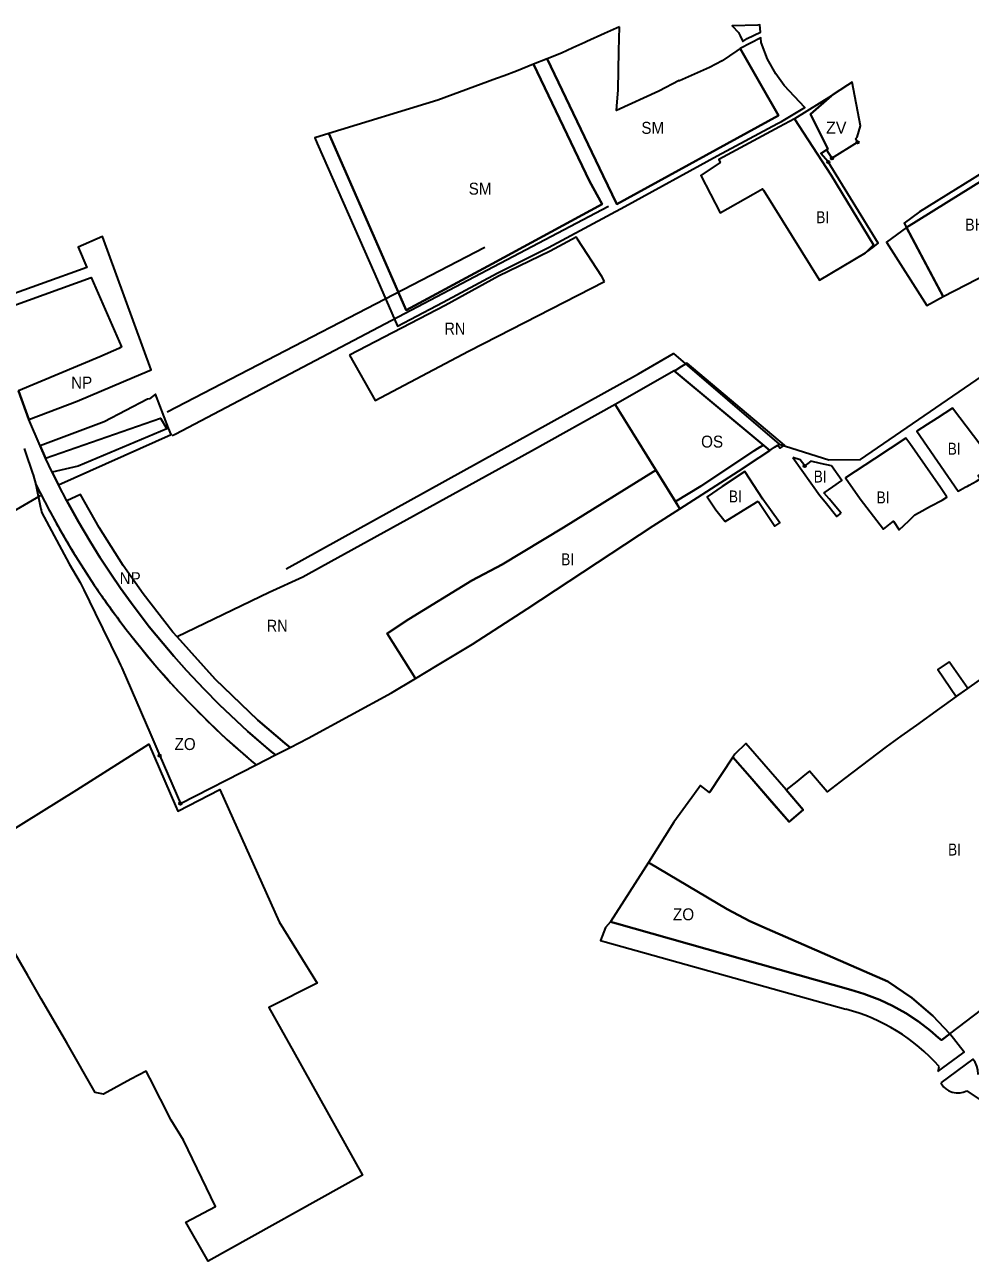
# Model space of a CAD drawing. Extents: x -650276 to -642489, y -1074311 to -1066658.
# Drawn here: x -649019 to -648072, y -1071627 to -1070387 of the extents above; entities that cross this region are included whole.
import ezdxf

# ---------------------------------------------------------------- set-up
doc = ezdxf.new("R2010")
doc.units = 0
doc.header["$LTSCALE"] = 4.8
doc.header["$PDMODE"] = 32
doc.header["$PDSIZE"] = 2.4
for name, color, linetype, lineweight in [('1', 7, 'Continuous', 35), ('15', 7, 'Continuous', 35), ('18', 7, 'Continuous', 35), ('2', 7, 'Continuous', 35), ('24', 7, 'Continuous', 35), ('40', 7, 'Continuous', 35), ('42', 7, 'Continuous', 35), ('48', 7, 'Continuous', 35), ('54', 7, 'Continuous', 35), ('7', 7, 'Continuous', 35), ('9', 7, 'Continuous', 35)]:
    doc.layers.add(name, color=color, linetype=linetype, lineweight=lineweight)
doc.layers.add('62', color=7, linetype='Continuous')
doc.layers.add('63', color=7, linetype='Continuous')

msp = doc.modelspace()

# ---------------------------------------------------------------- linework, layer by layer
at = {"layer": '1'}
msp.add_lwpolyline([(-648098.637, -1070659.682), (-648007.838, -1070612.851), (-648019, -1070518), (-648135.47, -1070590.61), (-648105.98, -1070645.91)], close=True, dxfattribs=at)
at = {"layer": '15'}
for p, q in [((-648303.631, -1070834.849), (-648283.19, -1070821.23)), ((-648272.453, -1070814.072), (-648271.1, -1070813.17))]:
    msp.add_line(p, q, dxfattribs=at)
for points in [[(-648303.705, -1070395.035), (-648302.028, -1070398.436), (-648299.32, -1070403.93), (-648295.18, -1070401.23), (-648281.907, -1070394.762), (-648282.582, -1070387.276), (-648284.37, -1070387.85), (-648310.275, -1070388.476)], [(-648550.72, -1070626.869), (-648636.757, -1070673.431), (-648655.178, -1070631.294), (-648714.161, -1070496.376), (-648728.255, -1070500.709), (-648725.835, -1070506.221), (-648668.207, -1070637.453), (-648645.331, -1070689.546), (-648632.652, -1070682.82), (-648599.66, -1070665.32), (-648545.76, -1070636.22), (-648494.04, -1070610.73), (-648417.855, -1070569.57), (-648325.21, -1070518.84), (-648264.56, -1070486.34), (-648260.57, -1070484.2), (-648237.475, -1070470.361), (-648257.96, -1070448.17), (-648266.416, -1070436.404), (-648274.808, -1070421.647), (-648280.974, -1070405.11), (-648281.388, -1070400.523), (-648302.01, -1070411.05), (-648282.01, -1070446.35), (-648263.859, -1070478.393), (-648425.835, -1070567.021), (-648439.409, -1070538.729), (-648495.666, -1070421.476), (-648509.227, -1070426.957), (-648452.97, -1070544.21), (-648440.531, -1070567.236)], [(-648007.838, -1070612.851), (-647999.588, -1070608.596), (-648002, -1070588), (-648010.831, -1070512.588), (-647999.756, -1070505.655), (-647981.81, -1070496.06), (-647950.48, -1070482.79), (-647917.98, -1070472.47), (-647918.54, -1070468.61), (-647918.95, -1070462.36), (-647923.53, -1070462.75), (-647923.247, -1070465.749), (-647953.251, -1070475.276), (-647985.19, -1070488.804), (-647991.539, -1070492.016), (-648005.668, -1070434.145), (-648014.63, -1070439.36), (-648000.442, -1070499.336), (-648019.789, -1070511.293), (-648050.38, -1070530.2), (-648122.57, -1070575), (-648137.78, -1070586.25), (-648135.47, -1070590.61), (-648019, -1070518)], [(-648135.47, -1070590.61), (-648155.582, -1070605.295), (-648115.057, -1070668.651), (-648098.637, -1070659.682)], [(-648092.72, -1071025.89), (-648104.12, -1071033.78), (-648085.73, -1071060.92), (-648074.12, -1071052.75)], [(-648238.84, -1071174.33), (-648256.04, -1071154.5), (-648278.39, -1071128.74), (-648296.34, -1071108.04), (-648307.33, -1071118.47), (-648309.41, -1071121.655), (-648292.587, -1071141.054), (-648270.236, -1071166.815), (-648253.126, -1071186.542)]]:
    msp.add_lwpolyline(points, close=True, dxfattribs=at)
for points in [[(-648213.87, -1070524.8), (-648221.359, -1070516.349), (-648215.48, -1070512.59), (-648214.34, -1070511.86), (-648231.53, -1070476.99), (-648210.48, -1070458.42), (-648247.67, -1070481.57), (-648211, -1070538), (-648168.575, -1070607.847), (-648176.54, -1070616.09)], [(-648176.54, -1070616.09), (-648169.28, -1070610.49), (-648163.8, -1070606.27), (-648213.87, -1070524.8), (-648221.359, -1070516.349), (-648215.48, -1070512.59), (-648214.34, -1070511.86), (-648231.53, -1070476.99), (-648210.48, -1070458.42), (-648247.67, -1070481.57), (-648211, -1070538)], [(-648176.54, -1070616.09), (-648169.28, -1070610.49), (-648163.8, -1070606.27), (-648213.87, -1070524.8)], [(-648211, -1070538), (-648168.575, -1070607.847), (-648176.54, -1070616.09)], [(-648271.1, -1070813.17), (-648267.8, -1070810.96), (-648264.38, -1070808.66), (-648262.15, -1070811.96), (-648257.61, -1070808.91), (-648355.275, -1070726.455), (-648360.83, -1070729.87), (-648366.739, -1070733.501), (-648368.163, -1070734.376), (-648272.453, -1070814.072)], [(-648283.19, -1070821.23), (-648272.45, -1070814.075), (-648278.832, -1070808.761), (-648282.44, -1070810.84), (-648287.74, -1070814.32)], [(-648287.74, -1070814.32), (-648341.58, -1070849.98), (-648366.98, -1070865.44)], [(-648366.98, -1070865.44), (-648362.519, -1070872.788), (-648303.631, -1070834.849)]]:
    msp.add_lwpolyline(points, dxfattribs=at)
msp.add_point((-648213.87, -1070524.8), dxfattribs=at)
at = {"layer": '18'}
for points in [[(-648423.005, -1070389.357), (-648438.21, -1070396.22), (-648455.85, -1070404.19), (-648457.94, -1070405.13), (-648469.77, -1070410.47)], [(-648363.1, -1070443.1), (-648383.61, -1070453.86), (-648426.05, -1070473.34), (-648425.71, -1070468.87), (-648424.47, -1070452.7), (-648423.56, -1070413.35), (-648423.005, -1070389.357)], [(-648469.77, -1070410.47), (-648481.18, -1070415.62), (-648495.666, -1070421.476), (-648439.409, -1070538.729)], [(-648439.409, -1070538.729), (-648425.835, -1070567.021), (-648263.859, -1070478.393), (-648282.01, -1070446.35), (-648302.01, -1070411.05)], [(-648302.01, -1070411.05), (-648305.39, -1070413.38), (-648320.24, -1070423.64), (-648332.97, -1070430.18), (-648362.79, -1070443.63), (-648363.1, -1070443.1)]]:
    msp.add_lwpolyline(points, dxfattribs=at)
msp.add_lwpolyline([(-648636.757, -1070673.431), (-648550.72, -1070626.869), (-648440.531, -1070567.236), (-648452.97, -1070544.21), (-648509.227, -1070426.957), (-648526.28, -1070433.85), (-648538.611, -1070438.388), (-648546.377, -1070441.246), (-648604.92, -1070462.79), (-648714.161, -1070496.376), (-648655.178, -1070631.294)], close=True, dxfattribs=at)
at = {"layer": '2'}
for points in [[(-648247.67, -1070481.57), (-648262.69, -1070489.67), (-648323.59, -1070522.48), (-648322.18, -1070525.44), (-648341.41, -1070538.42), (-648322.16, -1070575.76), (-648289.22, -1070557.15), (-648279.736, -1070551.783), (-648278.89, -1070553.14), (-648222.58, -1070643.48), (-648176.54, -1070616.09), (-648168.575, -1070607.847), (-648211, -1070538)], [(-648114.77, -1070788.08), (-648125.2, -1070794.79), (-648083.65, -1070854.89), (-648076.73, -1070851.07), (-648074.41, -1070849.79), (-648072.59, -1070848.79), (-648065.35, -1070844.8), (-648061.52, -1070842.68), (-648063.76, -1070839.49), (-648056.61, -1070834.26), (-648047.17, -1070827.35), (-648089.27, -1070771.57), (-648104.78, -1070781.65)], [(-648167.6, -1070822.53), (-648196.65, -1070841.7), (-648181.75, -1070862.74), (-648158.58, -1070892.98), (-648148.34, -1070884.92), (-648142.79, -1070893.78), (-648133.14, -1070884.6), (-648127, -1070878.75), (-648122.72, -1070876.44), (-648111.24, -1070870.11), (-648099.85, -1070863.82), (-648094.9, -1070861.09), (-648095.42, -1070860.3), (-648101.45, -1070851.34), (-648132.03, -1070807.05), (-648136.08, -1070801.79), (-648151.77, -1070812.11)], [(-648540.7, -1070928.6), (-648571.14, -1070944.67), (-648634.07, -1070983.17), (-648655.76, -1070997.5), (-648627.39, -1071042.65), (-648605.3, -1071029.34), (-648570.23, -1071008.2), (-648515.46, -1070972.94), (-648389.33, -1070889.79), (-648362.519, -1070872.788), (-648386.587, -1070833.807), (-648479.18, -1070891.26)]]:
    msp.add_lwpolyline(points, close=True, dxfattribs=at)
for points in [[(-648237.46, -1070829.68), (-648241.96, -1070823.46), (-648249.5, -1070821.08)], [(-648249.5, -1070821.08), (-648222.158, -1070859.221), (-648217.1, -1070865.56), (-648205.18, -1070880.5), (-648200.86, -1070877.05)], [(-648210.517, -1070829.445), (-648221.58, -1070827.03), (-648231.22, -1070824.92), (-648237.46, -1070829.68)], [(-648284.02, -1070864.91), (-648267.24, -1070889.9), (-648262.4, -1070886.58), (-648279.39, -1070862.98), (-648297.39, -1070835.36), (-648320.02, -1070850.16), (-648335.19, -1070860.49), (-648326.41, -1070873.55), (-648317.14, -1070885.48)], [(-648218.11, -1070856.44), (-648209.37, -1070850.44), (-648200.17, -1070844.094), (-648210.517, -1070829.445)], [(-648200.86, -1070877.05), (-648212.94, -1070862.74), (-648217.85, -1070856.93), (-648218.11, -1070856.44)], [(-648317.14, -1070885.48), (-648285.72, -1070865.96), (-648284.02, -1070864.91)], [(-648062.53, -1071044.59), (-648085.73, -1071060.92), (-648097.61, -1071069.37), (-648102.55, -1071072.86), (-648125.53, -1071089.51), (-648141.12, -1071100.71), (-648155.77, -1071111.23), (-648172.48, -1071123.95), (-648197.57, -1071143.03), (-648215.08, -1071156.35), (-648232.8, -1071135.6), (-648237.46, -1071139.38), (-648245.49, -1071145.91), (-648256.04, -1071154.5), (-648238.84, -1071174.33), (-648253.126, -1071186.542), (-648292.587, -1071141.054), (-648309.41, -1071121.655), (-648333.002, -1071157.07), (-648341.943, -1071150.071), (-648347.949, -1071158.385), (-648368.48, -1071186.81), (-648394.104, -1071227.17), (-648315.127, -1071274.052), (-648292.406, -1071286.112), (-648274.918, -1071293.751), (-648154.21, -1071346.477), (-648130, -1071363), (-648109, -1071381), (-648091.92, -1071399.07), (-648060.01, -1071374.69)], [(-649055.64, -1071209.682), (-648966.9, -1071154.34), (-648894.684, -1071108.668), (-648867.88, -1071170.58), (-648865.61, -1071175.825), (-648823.531, -1071154.018), (-648764.17, -1071286.65), (-648725.85, -1071348.28), (-648774.371, -1071372.773), (-648749.854, -1071416.727), (-648680.709, -1071540.691), (-648835.095, -1071627.059), (-648857.66, -1071587.83), (-648827.998, -1071572.04), (-648859.97, -1071505.55), (-648872.28, -1071485.58), (-648893.65, -1071443.47), (-648897.169, -1071436.535), (-648912.69, -1071444.48), (-648940.23, -1071459.65), (-648948.27, -1071457.92), (-648976.99, -1071408.03), (-649002.42, -1071363.86), (-649015.83, -1071340.58), (-649031.91, -1071312.65)]]:
    msp.add_lwpolyline(points, dxfattribs=at)
msp.add_point((-648237.46, -1070829.68), dxfattribs=at)
at = {"layer": '24'}
for points in [[(-649019.48, -1070812.18), (-649018.48, -1070815.18), (-649011.24, -1070836.79), (-649010.67, -1070838.5), (-649007.885, -1070848.153), (-648994.464, -1070873.974), (-648982.467, -1070895.704), (-648970.712, -1070915.663), (-648960.268, -1070932.429), (-648949.389, -1070949.031), (-648939.232, -1070963.818), (-648918.601, -1070991.969), (-648896.068, -1071020.184), (-648886.874, -1071031.044), (-648874.793, -1071044.773), (-648863.847, -1071056.723), (-648851.175, -1071069.886), (-648838.696, -1071082.562), (-648823.087, -1071097.562), (-648816.379, -1071103.782), (-648806.239, -1071112.938), (-648797, -1071121), (-648790.23, -1071126.818), (-648787.207, -1071129.363), (-648767.824, -1071119.455), (-648771.725, -1071116.233), (-648781.806, -1071107.721), (-648795.407, -1071095.8), (-648824.292, -1071068.677), (-648839.273, -1071053.556), (-648856.883, -1071034.761), (-648869.629, -1071020.411), (-648880.44, -1071007.703), (-648894.164, -1070990.806), (-648902.714, -1070979.812), (-648912.396, -1070966.893), (-648922.92, -1070952.242), (-648932.78, -1070937.887), (-648943.414, -1070921.659), (-648953.605, -1070905.299), (-648965.093, -1070885.794), (-648976.834, -1070864.527), (-648985.145, -1070848.538), (-648991.386, -1070835.954), (-648998.132, -1070821.723), (-649003.641, -1070809.566), (-649014.888, -1070782.994), (-649025.129, -1070754.377)], [(-648103.894, -1071436.836), (-648079.108, -1071418.564), (-648077.53, -1071417.4), (-648091.92, -1071399.07), (-648100.438, -1071405.517), (-648103.268, -1071402.88), (-648111.646, -1071395.618), (-648123.313, -1071386.696), (-648136.263, -1071378.194), (-648149.571, -1071370.788), (-648162.084, -1071364.918), (-648178.158, -1071358.781), (-648191.25, -1071354.858), (-648426.18, -1071288.32), (-648432.093, -1071286.645), (-648437.16, -1071292.53), (-648442.191, -1071305.453), (-648437.454, -1071306.778), (-648196.236, -1071374.226)], [(-648063.593, -1071439.723), (-648063.862, -1071435.078), (-648064.838, -1071431.28), (-648066.623, -1071427.592), (-648069.022, -1071424.443), (-648101.203, -1071448.31)], [(-648101.203, -1071448.31), (-648098.259, -1071452.196), (-648096.014, -1071454.192), (-648093.059, -1071456.066), (-648089.539, -1071457.489), (-648085.585, -1071458.248), (-648081.642, -1071458.215), (-648078.539, -1071457.636), (-648074.86, -1071456.248)], [(-648074.86, -1071456.248), (-648027.562, -1071487.894)]]:
    msp.add_lwpolyline(points, dxfattribs=at)
for centre, radius, start, end in [((-648244.965, -1071557.871), 190, 41.59858, 75.13936), ((-648083.781, -1071438.172), 20.157, 161.35794, 176.20098)]:
    msp.add_arc(centre, radius, start, end, dxfattribs=at)
at = {"layer": '40'}
msp.add_line((-648210.19, -1070521.07), (-648184.54, -1070505.07), dxfattribs=at)
for points in [[(-648184.54, -1070505.07), (-648186.088, -1070501.313), (-648184.791, -1070500.073), (-648181.386, -1070488.724), (-648189.93, -1070444.71), (-648194.56, -1070447.8), (-648194.56, -1070447.799), (-648209.82, -1070457.98), (-648210.48, -1070458.42), (-648231.53, -1070476.99), (-648214.34, -1070511.86)], [(-648214.34, -1070511.86), (-648215.48, -1070512.59), (-648210.19, -1070521.07)]]:
    msp.add_lwpolyline(points, dxfattribs=at)
for p in [(-648184.54, -1070505.07), (-648210.19, -1070521.07)]:
    msp.add_point(p, dxfattribs=at)
at = {"layer": '42'}
for p, q in [((-648883.73, -1071120.13), (-648862.97, -1071168.09)), ((-648862.97, -1071168.09), (-648787.207, -1071129.363)), ((-648394.104, -1071227.17), (-648432.093, -1071286.645))]:
    msp.add_line(p, q, dxfattribs=at)
for points in [[(-649002.97, -1070857.609), (-649007.885, -1070848.153), (-649003.1, -1070871.35), (-649002.82, -1070872.69), (-649002.62, -1070873.69), (-649002.15, -1070875.96), (-648974.4, -1070927.77), (-648963.5, -1070946.45), (-648959.92, -1070953.73), (-648948.29, -1070977.37), (-648924.92, -1071024.89), (-648922.98, -1071029.49), (-648921.87, -1071032.04), (-648892.82, -1071099.15), (-648883.73, -1071120.13)], [(-648994.42, -1070874.053), (-648994.464, -1070873.974), (-648994.52, -1070873.867)], [(-648982.403, -1070895.812), (-648982.467, -1070895.704), (-648982.524, -1070895.601)], [(-648970.64, -1070915.778), (-648970.712, -1070915.663), (-648970.771, -1070915.564)], [(-648960.194, -1070932.542), (-648960.268, -1070932.429), (-648960.34, -1070932.313)], [(-648949.345, -1070949.096), (-648949.389, -1070949.031), (-648949.428, -1070948.972)], [(-648939.179, -1070963.89), (-648939.232, -1070963.818), (-648939.33, -1070963.675)], [(-648918.464, -1070992.141), (-648918.601, -1070991.969), (-648918.737, -1070991.784)], [(-648292.406, -1071286.112), (-648315.127, -1071274.052), (-648394.104, -1071227.17), (-648432.093, -1071286.645)], [(-648432.093, -1071286.645), (-648426.18, -1071288.32), (-648191.25, -1071354.858)], [(-648091.92, -1071399.07), (-648109, -1071381), (-648130, -1071363), (-648154.21, -1071346.477), (-648274.918, -1071293.751), (-648292.406, -1071286.112)], [(-648191.25, -1071354.858), (-648178.158, -1071358.781), (-648162.084, -1071364.918), (-648149.571, -1071370.788), (-648136.263, -1071378.194), (-648123.313, -1071386.696), (-648111.646, -1071395.618), (-648103.268, -1071402.88), (-648100.438, -1071405.517), (-648091.92, -1071399.07)]]:
    msp.add_lwpolyline(points, dxfattribs=at)
for start, end in [(206.85611, 208.07207), (208.08607, 209.71957), (209.73567, 211.25686), (211.27351, 212.56631), (212.58435, 213.8879), (213.89777, 215.07157), (215.08899, 217.38409), (217.41391, 230.04071)]:
    msp.add_arc((-648232.695, -1070467.567), 863.398, start, end, dxfattribs=at)
for p in [(-648883.73, -1071120.13), (-648862.97, -1071168.09)]:
    msp.add_point(p, dxfattribs=at)
at = {"layer": '48'}
msp.add_line((-648894.164, -1070990.806), (-648880.44, -1071007.703), dxfattribs=at)
for points in [[(-649014.888, -1070782.994), (-648966.35, -1070764.7), (-648908.94, -1070740.19), (-648892.215, -1070733.293), (-648927.2, -1070637.98), (-648941.064, -1070599.735), (-648965.569, -1070610.382), (-648956.687, -1070630.825), (-649050.081, -1070663.981), (-649047.11, -1070674.743), (-648952.455, -1070640.564), (-648922.196, -1070710.207), (-648924.668, -1070712.022), (-648943.837, -1070720.104), (-649025.129, -1070754.377)], [(-648985.145, -1070848.538), (-648872.375, -1070798.112), (-648874.87, -1070791.61), (-648887.84, -1070757.84), (-648894.08, -1070762.22), (-648896.11, -1070762.73), (-648939.5, -1070785.4), (-649003.641, -1070809.566), (-648998.132, -1070821.723), (-648882.919, -1070781.673), (-648876.64, -1070792.6), (-648965.475, -1070829.829), (-648991.386, -1070835.954)]]:
    msp.add_lwpolyline(points, close=True, dxfattribs=at)
for points in [[(-648866.341, -1071000.881), (-648870.479, -1070996.265), (-648900.337, -1070957.964), (-648920.293, -1070929.567), (-648944.376, -1070891.404), (-648963.107, -1070858.328), (-648976.834, -1070864.527)], [(-648976.834, -1070864.527), (-648965.093, -1070885.794), (-648953.605, -1070905.299), (-648943.414, -1070921.659), (-648932.78, -1070937.887), (-648922.92, -1070952.242), (-648912.396, -1070966.893), (-648894.164, -1070990.806)], [(-648880.44, -1071007.703), (-648869.629, -1071020.411), (-648856.883, -1071034.761), (-648839.273, -1071053.556), (-648824.292, -1071068.677), (-648795.407, -1071095.8), (-648777.641, -1071111.238), (-648771.725, -1071116.233), (-648767.824, -1071119.455), (-648752.967, -1071111.861), (-648758.423, -1071107.756), (-648785.386, -1071084.634), (-648828.353, -1071043.265), (-648866.341, -1071000.881)]]:
    msp.add_lwpolyline(points, dxfattribs=at)
at = {"layer": '54'}
for p, q in [((-648876.429, -1070775.252), (-648558.121, -1070610.206)), ((-649003.638, -1070859.543), (-649266.084, -1071012.071))]:
    msp.add_line(p, q, dxfattribs=at)
for points in [[(-648433.898, -1070569.36), (-648868.299, -1070798.03), (-648871.326, -1070799.464)], [(-648756.915, -1070932.76), (-648403.845, -1070737.419), (-648368.964, -1070716.905), (-648263.103, -1070807.79), (-648213.358, -1070823.563), (-648181.392, -1070823.076), (-647966.625, -1070675.686), (-647777.125, -1070608.309)]]:
    msp.add_lwpolyline(points, dxfattribs=at)
at = {"layer": '7'}
for points in [[(-648438.13, -1070644.73), (-648440.8, -1070639.72), (-648465.28, -1070602.24), (-648466.61, -1070600.21), (-648492.47, -1070614.2), (-648544.42, -1070639.42), (-648597.74, -1070668.62), (-648693.45, -1070718.46)], [(-648693.45, -1070718.46), (-648667.72, -1070764.15), (-648574.27, -1070714.5), (-648544.906, -1070699.451), (-648438.13, -1070644.73)]]:
    msp.add_lwpolyline(points, dxfattribs=at)
msp.add_lwpolyline([(-648866.341, -1071000.881), (-648828.353, -1071043.265), (-648785.386, -1071084.634), (-648758.423, -1071107.756), (-648752.967, -1071111.861), (-648734.849, -1071102.599), (-648651.375, -1071057.109), (-648627.39, -1071042.65), (-648655.76, -1070997.5), (-648634.07, -1070983.17), (-648571.14, -1070944.67), (-648540.7, -1070928.6), (-648479.18, -1070891.26), (-648386.587, -1070833.807), (-648427.25, -1070767.95), (-648511.09, -1070814.7), (-648721.54, -1070930.88), (-648740.25, -1070941.21), (-648774.23, -1070956.42)], close=True, dxfattribs=at)
at = {"layer": '9'}
msp.add_lwpolyline([(-648368.163, -1070734.376), (-648427.25, -1070767.95), (-648366.98, -1070865.44), (-648341.58, -1070849.98), (-648287.74, -1070814.32), (-648282.44, -1070810.84), (-648278.832, -1070808.761)], close=True, dxfattribs=at)

# ---------------------------------------------------------------- texts
at = {"layer": '62'}
msp.add_text('ZV', height=12, dxfattribs=at).set_placement((-648216.069, -1070496.39))
for s, width, p in [('SM', 0.95, (-648574.138, -1070557.646)), ('BI', 0.85, (-648225.838, -1070586.256)), ('BH', 0.9, (-648076.769, -1070593.709)), ('RN', 0.9, (-648598.428, -1070697.883)), ('NP', 0.95, (-648972.583, -1070752.041)), ('OS', 0.95, (-648341.265, -1070811.272)), ('BI', 0.85, (-648094.127, -1070818.398)), ('BI', 0.85, (-648228.397, -1070846.265)), ('BI', 0.85, (-648313.397, -1070866.265)), ('BI', 0.85, (-648165.397, -1070867.265)), ('BI', 0.85, (-648481.397, -1070929.265)), ('NP', 0.95, (-648923.942, -1070948.157)), ('RN', 0.9, (-648776.428, -1070995.883)), ('ZO', 0.95, (-648868.886, -1071114.486)), ('BI', 0.85, (-648093.764, -1071220.263)), ('ZO', 0.95, (-648369.423, -1071285.188))]:
    msp.add_text(s, height=12, dxfattribs=dict(at, width=width)).set_placement(p)
at = {"layer": '63', "width": 0.95}
msp.add_text('SM', height=12, dxfattribs=at).set_placement((-648401.138, -1070496.646))

doc.saveas('drawing.dxf')
